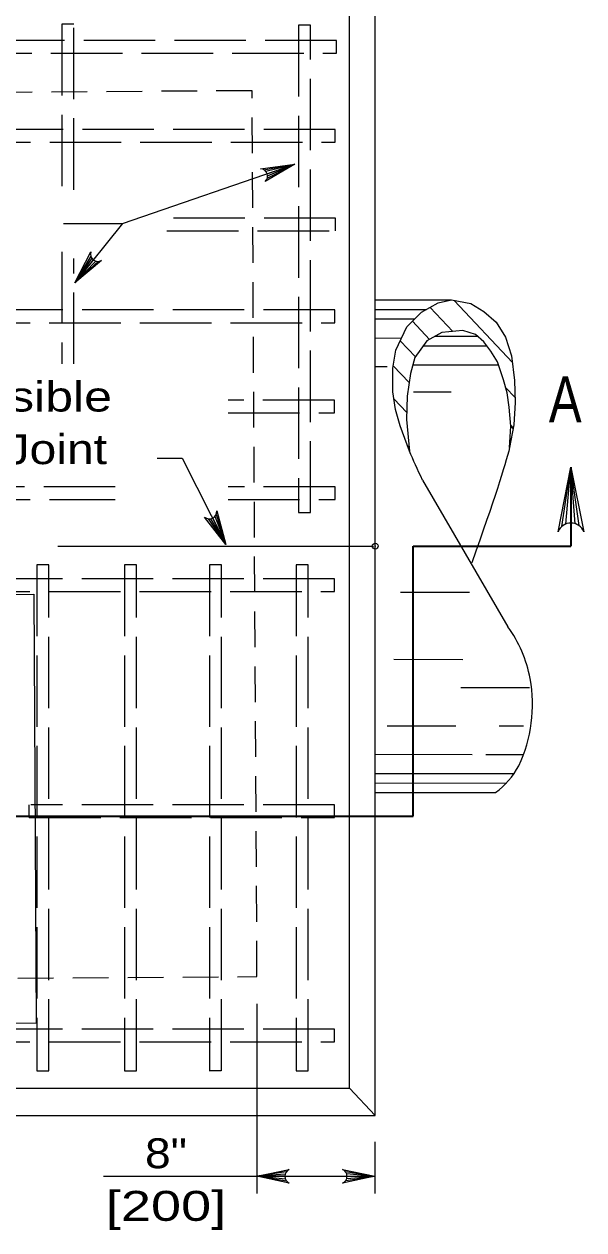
# Model space of a CAD drawing. Extents: x 1329.9 to 1363.9, y 715.5 to 737.5.
# Drawn here: x 1351.66 to 1354.57, y 727.53 to 733.81 of the extents above; entities that cross this region are included whole.
import ezdxf
from ezdxf.enums import TextEntityAlignment as Align

# ---------------------------------------------------------------- set-up
doc = ezdxf.new("R2010")
doc.units = 0
doc.header["$LTSCALE"] = 0.062
doc.header["$PDMODE"] = 32
doc.header["$PDSIZE"] = 0.031
doc.linetypes.add('LONG_DASHED', pattern=[7.5, 6, -1.5])
doc.linetypes.add('MEDIUM_DASHED', pattern=[4.5, 3, -1.5])
doc.layers.add('1', color=7, linetype='Continuous', lineweight=13)

msp = doc.modelspace()

# ---------------------------------------------------------------- linework, layer by layer
at = {"layer": '1', "lineweight": 25}
for p, q in [((1353.483, 728.1235), (1353.483, 734.1075)), ((1353.34842, 728.26592), (1353.34842, 733.96508)), ((1353.48483, 732.37325), (1353.88033, 732.37267)), ((1353.81025, 732.357), (1353.88033, 732.37267)), ((1353.64733, 732.23333), (1353.7245, 732.30933)), ((1354.12017, 732.04992), (1354.08542, 732.106)), ((1354.21208, 731.839), (1354.2045, 731.722)), ((1353.65158, 731.61317), (1353.65992, 731.60408)), ((1353.7295, 731.43308), (1354.174, 730.67017)), ((1351.83017, 731.09017), (1353.47458, 731.09017)), ((1353.48108, 729.807), (1354.10975, 729.80608)), ((1347.96533, 728.26592), (1353.34842, 728.26592)), ((1353.34842, 728.26592), (1353.483, 728.1235)), ((1347.83075, 728.1235), (1353.483, 728.1235))]:
    msp.add_line(p, q, dxfattribs=at)
at = {"layer": '1', "linetype": 'LONG_DASHED'}
for p, q in [((1351.91383, 733.80933), (1351.85117, 733.80933)), ((1351.85117, 733.80933), (1351.85117, 732.94675)), ((1351.91383, 732.94675), (1351.91383, 733.80933)), ((1353.27692, 732.79808), (1352.39883, 732.79808)), ((1353.27692, 732.73175), (1353.27692, 732.79808)), ((1352.39883, 732.73175), (1353.27692, 732.73175)), ((1351.85117, 732.62367), (1351.85117, 732.03892)), ((1351.91383, 732.03892), (1351.91383, 732.5885)), ((1353.2705, 731.85117), (1352.71683, 731.85117)), ((1353.2705, 731.78483), (1353.2705, 731.85117)), ((1352.71683, 731.78483), (1353.2705, 731.78483)), ((1352.12917, 731.39942), (1348.011, 731.39942)), ((1353.27408, 731.39942), (1352.71683, 731.39942)), ((1353.27408, 731.33308), (1353.27408, 731.39942)), ((1348.011, 731.33308), (1352.12917, 731.33308)), ((1352.71683, 731.33308), (1353.27408, 731.33308)), ((1351.78358, 730.99317), (1351.72092, 730.99317)), ((1351.72092, 730.99317), (1351.72092, 728.35742)), ((1351.78358, 728.35742), (1351.78358, 730.99317)), ((1352.241, 730.99317), (1352.17833, 730.99317)), ((1352.17833, 730.99317), (1352.17833, 728.35742)), ((1352.241, 728.35742), (1352.241, 730.99317)), ((1352.68258, 730.99317), (1352.61992, 730.99317)), ((1352.61992, 730.99317), (1352.61992, 728.35742)), ((1352.68258, 728.35742), (1352.68258, 730.99317)), ((1353.13433, 730.99317), (1353.07167, 730.99317)), ((1353.07167, 730.99317), (1353.07167, 728.35742)), ((1353.13433, 728.35742), (1353.13433, 730.99317)), ((1353.27142, 730.91975), (1351.21892, 730.91975)), ((1353.27142, 729.74258), (1351.68925, 729.74258)), ((1353.27142, 729.67625), (1353.27142, 729.74258)), ((1351.68167, 729.67625), (1353.27142, 729.67625)), ((1351.72092, 728.35742), (1351.78358, 728.35742)), ((1352.17833, 728.35742), (1352.241, 728.35742)), ((1352.61808, 728.35875), (1352.68067, 728.35875)), ((1353.07167, 728.35742), (1353.13433, 728.35742))]:
    msp.add_line(p, q, dxfattribs=at)
at = {"layer": '1'}
for p, q in [((1352.90392, 733.05092), (1353.06533, 733.08017)), ((1352.91308, 733.04308), (1353.06533, 733.08017)), ((1352.9205, 733.03033), (1353.06533, 733.08017)), ((1352.92108, 733.00683), (1353.06533, 733.08017)), ((1352.92258, 733.01908), (1353.06533, 733.08017)), ((1352.16667, 732.77117), (1351.9195, 732.46208)), ((1352.00208, 732.60133), (1351.9195, 732.46208)), ((1352.00742, 732.59008), (1351.9195, 732.46208)), ((1352.01517, 732.58175), (1351.9195, 732.46208)), ((1352.02825, 732.575), (1351.9195, 732.46208)), ((1352.04017, 732.57325), (1351.9195, 732.46208)), ((1353.7245, 732.30933), (1353.81025, 732.357)), ((1353.88033, 732.37267), (1353.98033, 732.35325)), ((1353.89325, 732.36992), (1354.19717, 732.04742)), ((1353.48467, 732.32358), (1353.74925, 732.32308)), ((1353.76842, 732.33367), (1353.88667, 732.20808)), ((1353.48467, 732.27392), (1353.68817, 732.2735)), ((1353.59067, 732.1115), (1353.64733, 732.23333)), ((1353.67675, 732.26208), (1353.76625, 732.16708)), ((1353.48458, 732.17442), (1353.61992, 732.17425)), ((1353.6135, 732.16033), (1353.6925, 732.07642)), ((1353.795, 732.18358), (1354.01642, 732.18333)), ((1353.73333, 732.134), (1354.06483, 732.13342)), ((1353.57692, 732.03017), (1353.65975, 731.94217)), ((1353.68908, 732.07192), (1353.66692, 731.98875)), ((1353.67925, 732.03467), (1354.12558, 732.034)), ((1353.48425, 732.02542), (1353.5445, 732.02517)), ((1354.162, 731.91567), (1354.21125, 731.8635)), ((1353.5805, 731.85758), (1353.64717, 731.78667)), ((1353.68183, 731.89383), (1353.87867, 731.8935)), ((1353.66167, 731.58508), (1353.6135, 731.71667)), ((1354.2045, 731.722), (1354.18292, 731.60425)), ((1354.2045, 731.722), (1354.18292, 731.60425)), ((1354.18292, 731.60425), (1354.18917, 731.71525)), ((1354.18292, 731.60425), (1354.18917, 731.71525)), ((1354.18892, 731.71833), (1354.2015, 731.70508)), ((1354.18908, 731.71325), (1354.20067, 731.70083)), ((1353.65917, 731.592), (1353.66133, 731.58983)), ((1354.18533, 731.64675), (1354.18992, 731.642)), ((1354.45492, 731.19317), (1354.502, 731.50142)), ((1354.47467, 731.20483), (1354.502, 731.50142)), ((1354.502, 731.21025), (1354.502, 731.50142)), ((1354.52358, 731.20708), (1354.502, 731.50142)), ((1354.54467, 731.19675), (1354.502, 731.50142)), ((1352.61375, 731.23258), (1352.70592, 731.09942)), ((1352.62617, 731.23275), (1352.70592, 731.09942)), ((1352.637, 731.23625), (1352.70592, 731.09942)), ((1352.64858, 731.24533), (1352.70592, 731.09942)), ((1352.65508, 731.2555), (1352.70592, 731.09942)), ((1353.6155, 730.85067), (1353.97317, 730.85017)), ((1353.58075, 730.50067), (1353.93842, 730.50017)), ((1353.92867, 730.35333), (1354.28633, 730.35283)), ((1353.54592, 730.15475), (1353.90358, 730.15425)), ((1354.12883, 730.15392), (1354.25567, 730.15375)), ((1353.4815, 730.00583), (1353.9885, 730.005)), ((1354.0585, 730.005), (1354.25542, 730.00467)), ((1353.48125, 729.90642), (1354.20592, 729.90525)), ((1353.48125, 729.85675), (1354.16575, 729.8555)), ((1351.68042, 729.74258), (1351.68042, 729.67625)), ((1353.48158, 727.98617), (1353.48158, 727.71833)), ((1353.01975, 727.83), (1352.86742, 727.80742)), ((1353.01458, 727.81883), (1352.86742, 727.80742)), ((1353.3275, 727.83233), (1353.48158, 727.80742)), ((1353.33333, 727.82192), (1353.48158, 727.80742)), ((1352.06892, 727.80742), (1353.48158, 727.80742)), ((1353.013, 727.80742), (1352.86742, 727.80742)), ((1353.01567, 727.79292), (1352.86742, 727.80742)), ((1353.0215, 727.7825), (1352.86742, 727.80742)), ((1353.32925, 727.78492), (1353.48158, 727.80742)), ((1353.33442, 727.796), (1353.48158, 727.80742)), ((1353.336, 727.80742), (1353.48158, 727.80742))]:
    msp.add_line(p, q, dxfattribs=at)
at = {"layer": '1', "lineweight": 35}
for p, q in [((1354.502, 731.50142), (1354.502, 731.09017)), ((1353.67975, 731.09017), (1354.502, 731.09017)), ((1353.67975, 729.68367), (1353.67975, 731.09017)), ((1349.47242, 729.68367), (1351.81367, 729.68367)), ((1351.81367, 729.68367), (1353.67975, 729.68367))]:
    msp.add_line(p, q, dxfattribs=at)
at = {"layer": '1', "linetype": 'MEDIUM_DASHED'}
msp.add_line((1348.47683, 728.82033), (1352.86742, 728.84767), dxfattribs=at)
at = {"layer": '1', "linetype": 'LONG_DASHED'}
for points in [[(1353.08417, 733.80442), (1353.08417, 731.2645), (1353.14683, 731.2645), (1353.14683, 733.80442)], [(1348.01858, 733.65842), (1353.28167, 733.65842), (1353.28167, 733.72475), (1348.01858, 733.72475)], [(1348.01208, 733.19508), (1353.27517, 733.19508), (1353.27517, 733.26133), (1348.01208, 733.26133)], [(1348.01017, 732.254), (1353.27325, 732.254), (1353.27325, 732.32033), (1348.01017, 732.32033)], [(1348.00833, 728.50783), (1353.27142, 728.50783), (1353.27142, 728.57417), (1348.00833, 728.57417)]]:
    msp.add_lwpolyline(points, close=True, dxfattribs=at)
at = {"layer": '1', "linetype": 'MEDIUM_DASHED'}
msp.add_lwpolyline([(1352.86742, 728.84767), (1352.84175, 733.46225), (1348.45, 733.435), (1348.47558, 728.82033)], dxfattribs=at)
at = {"layer": '1'}
for points in [[(1351.85958, 732.77117), (1352.16667, 732.77117), (1353.06533, 733.08017)], [(1352.88642, 733.05608), (1353.06533, 733.08017), (1352.90942, 732.98908)], [(1352.05775, 732.57825), (1351.9195, 732.46208), (1352.00242, 732.6225)], [(1354.08542, 732.106), (1354.04917, 732.15458), (1354.00517, 732.19317), (1353.93942, 732.21275), (1353.82992, 732.20325)], [(1354.16917, 731.88925), (1354.151, 731.95708), (1354.12017, 732.04992)], [(1354.19308, 732.08075), (1354.20892, 731.95333), (1354.21208, 731.839)], [(1352.34717, 731.549), (1352.47783, 731.549), (1352.70592, 731.09942)], [(1354.43475, 731.16492), (1354.502, 731.50142), (1354.56933, 731.16492)], [(1352.65792, 731.2735), (1352.70592, 731.09942), (1352.59467, 731.24167)], [(1352.86742, 728.70567), (1352.86742, 728.35742), (1352.86742, 727.71833)], [(1353.03567, 727.77183), (1352.86742, 727.80742), (1353.03567, 727.84308)], [(1353.31333, 727.84308), (1353.48158, 727.80742), (1353.31333, 727.77183)]]:
    msp.add_lwpolyline(points, dxfattribs=at)
at = {"layer": '1', "lineweight": 25}
for points in [[(1353.66167, 731.58508), (1353.6135, 731.71667), (1353.58942, 731.80258), (1353.57417, 731.8945), (1353.57483, 732.01767), (1353.59067, 732.1115), (1353.64733, 732.23333), (1353.7245, 732.30933), (1353.81025, 732.357), (1353.88033, 732.37267), (1353.98033, 732.35325), (1354.04933, 732.31267), (1354.11317, 732.257), (1354.16142, 732.17908), (1354.19308, 732.08075), (1354.20892, 731.95333), (1354.21208, 731.839), (1354.2045, 731.722)], [(1353.98033, 732.35325), (1354.04933, 732.31267), (1354.11317, 732.257), (1354.16142, 732.17908), (1354.19308, 732.08075)], [(1354.18917, 731.71525), (1354.18017, 731.81383), (1354.16917, 731.88925), (1354.151, 731.95708), (1354.12017, 732.04992), (1354.08542, 732.106), (1354.04917, 732.15458), (1354.00517, 732.19317), (1353.93942, 732.21275), (1353.82992, 732.20325), (1353.75117, 732.15875), (1353.68908, 732.07192), (1353.66692, 731.98875), (1353.64858, 731.87075), (1353.6465, 731.74892), (1353.66167, 731.58508)], [(1353.82992, 732.20325), (1353.75117, 732.15875), (1353.68908, 732.07192)], [(1353.6135, 731.71667), (1353.58942, 731.80258), (1353.57417, 731.8945), (1353.57483, 732.01767), (1353.59067, 732.1115)], [(1353.66692, 731.98875), (1353.64858, 731.87075), (1353.6465, 731.74892), (1353.66167, 731.58508)], [(1354.18917, 731.71525), (1354.18017, 731.81383), (1354.16917, 731.88925)]]:
    msp.add_lwpolyline(points, dxfattribs=at)
at = {"layer": '1', "linetype": 'LONG_DASHED'}
msp.add_lwpolyline([(1348.00833, 730.85342), (1353.27142, 730.85342), (1353.27142, 730.91975)], dxfattribs=at)
at = {"layer": '1'}
msp.add_lwpolyline([(1349.59067, 728.591), (1349.57825, 730.82658), (1351.70533, 730.83983), (1351.71775, 728.60417)], close=True, dxfattribs=at)
for centre, radius, start, end in [((1352.88441, 733.01793), 0.03822, 311.06479, 86.89092), ((1352.039, 732.61157), 0.03822, 163.43869, 299.26482), ((1352.61978, 731.27036), 0.03822, 228.81749, 4.64361), ((1354.50209, 731.13777), 0.07261, 22.08782, 157.91395)]:
    msp.add_arc(centre, radius, start, end, dxfattribs=at)
at = {"layer": '1', "lineweight": 25}
for centre, major_axis, start_param, end_param in [((1353.69011, 730.27565), (0, 0.64669), 4.9058986, 5.3686347), ((1353.62561, 730.26459), (0, 0.71577), 4.251341, 4.9027182), ((1353.8771, 730.16071), (0, -0.43184), 0.6070417, 1.0508543)]:
    msp.add_ellipse(centre, major_axis=major_axis, ratio=0.944544, start_param=start_param, end_param=end_param, dxfattribs=at)
at = {"layer": '1'}
for centre, major_axis in [((1353.04931, 727.80744), (0, 0.03844)), ((1353.29968, 727.80744), (0, -0.03844))]:
    msp.add_ellipse(centre, major_axis=major_axis, ratio=0.944544, start_param=0.3855052, end_param=2.7561184, dxfattribs=at)
at = {"layer": '1', "lineweight": 25}
for points in [[(1354.18292, 731.60425), (1354.15775, 731.50183), (1354.10483, 731.33733), (1353.9855, 731.003)], [(1353.7295, 731.43308), (1353.70283, 731.48908), (1353.6805, 731.53958), (1353.66167, 731.58508)]]:
    msp.add_open_spline(points, degree=3, dxfattribs=at)
at = {"layer": '1'}
msp.add_point((1353.483, 731.09017), dxfattribs=at)

# ---------------------------------------------------------------- texts
for s, height, width, p in [('A', 0.24, 0.8, (1354.47233, 731.73417)), ('8"', 0.156, 1.15, (1352.39383, 727.84925)), ('[200]', 0.156, 1.35, (1352.39383, 727.57517))]:
    msp.add_text(s, height=height, dxfattribs=dict(at, width=width)).set_placement(p, align=Align.CENTER)
for s, width, p in [('Permissible', 1.25, (1350.76508, 731.79125)), ('Const. Joint', 1.2, (1350.76508, 731.51717))]:
    msp.add_text(s, height=0.156, dxfattribs=dict(at, width=width)).set_placement(p)

doc.saveas('drawing.dxf')
